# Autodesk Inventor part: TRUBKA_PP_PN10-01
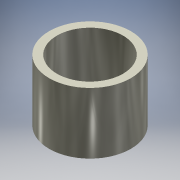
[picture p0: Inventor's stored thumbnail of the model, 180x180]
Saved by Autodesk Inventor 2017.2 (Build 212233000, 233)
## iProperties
Created: 2016-11
Part Number: TRUBKA_PP_PN10-01
Material: Polypropylen
Document SubType Name: Modeling
Designer: CADstudio
Mass: 1.45691 g
Surface Area: 19.2196 cm^2
Volume: 1.62059 cm^3
Density: 0.899 g/cm^3
Appearance: Hladká – popel
Vendor: KOWA
Categories: <MemberInstance><Categories><Category DisplayName="" InternalName="4347fa0f-2144-441d-94cd-e3e15c92b736" Mnemonic="TUBEANDPIPE"><CategoryParameter DisplayName="
Mass: 0,001
Title: TRUBKA PN10
Author: CADstudio
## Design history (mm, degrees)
sketch "Náčrt1"
  geometry: C1 r 10 at (0, 0); C2 r 8.1 at (0, 0); 1 further point
  constraints: 2 centre point, 2 coincident
  dimensions: "VNE" = 20 diameter of C1; "VNI" = 16.2 diameter of C2
extrude "Vysunutí1" new body sketch "Náčrt1" taper "d3" = 0 deg; distance "DELKA" = 15
node "Pracovní bod1"
node "Pracovní bod2"
node "Pracovní osa1"
node "Pracovní osa2"
node "Těleso1"
